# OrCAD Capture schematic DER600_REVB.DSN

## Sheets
1 PAGE1: size C; title: DER 802; rev: A
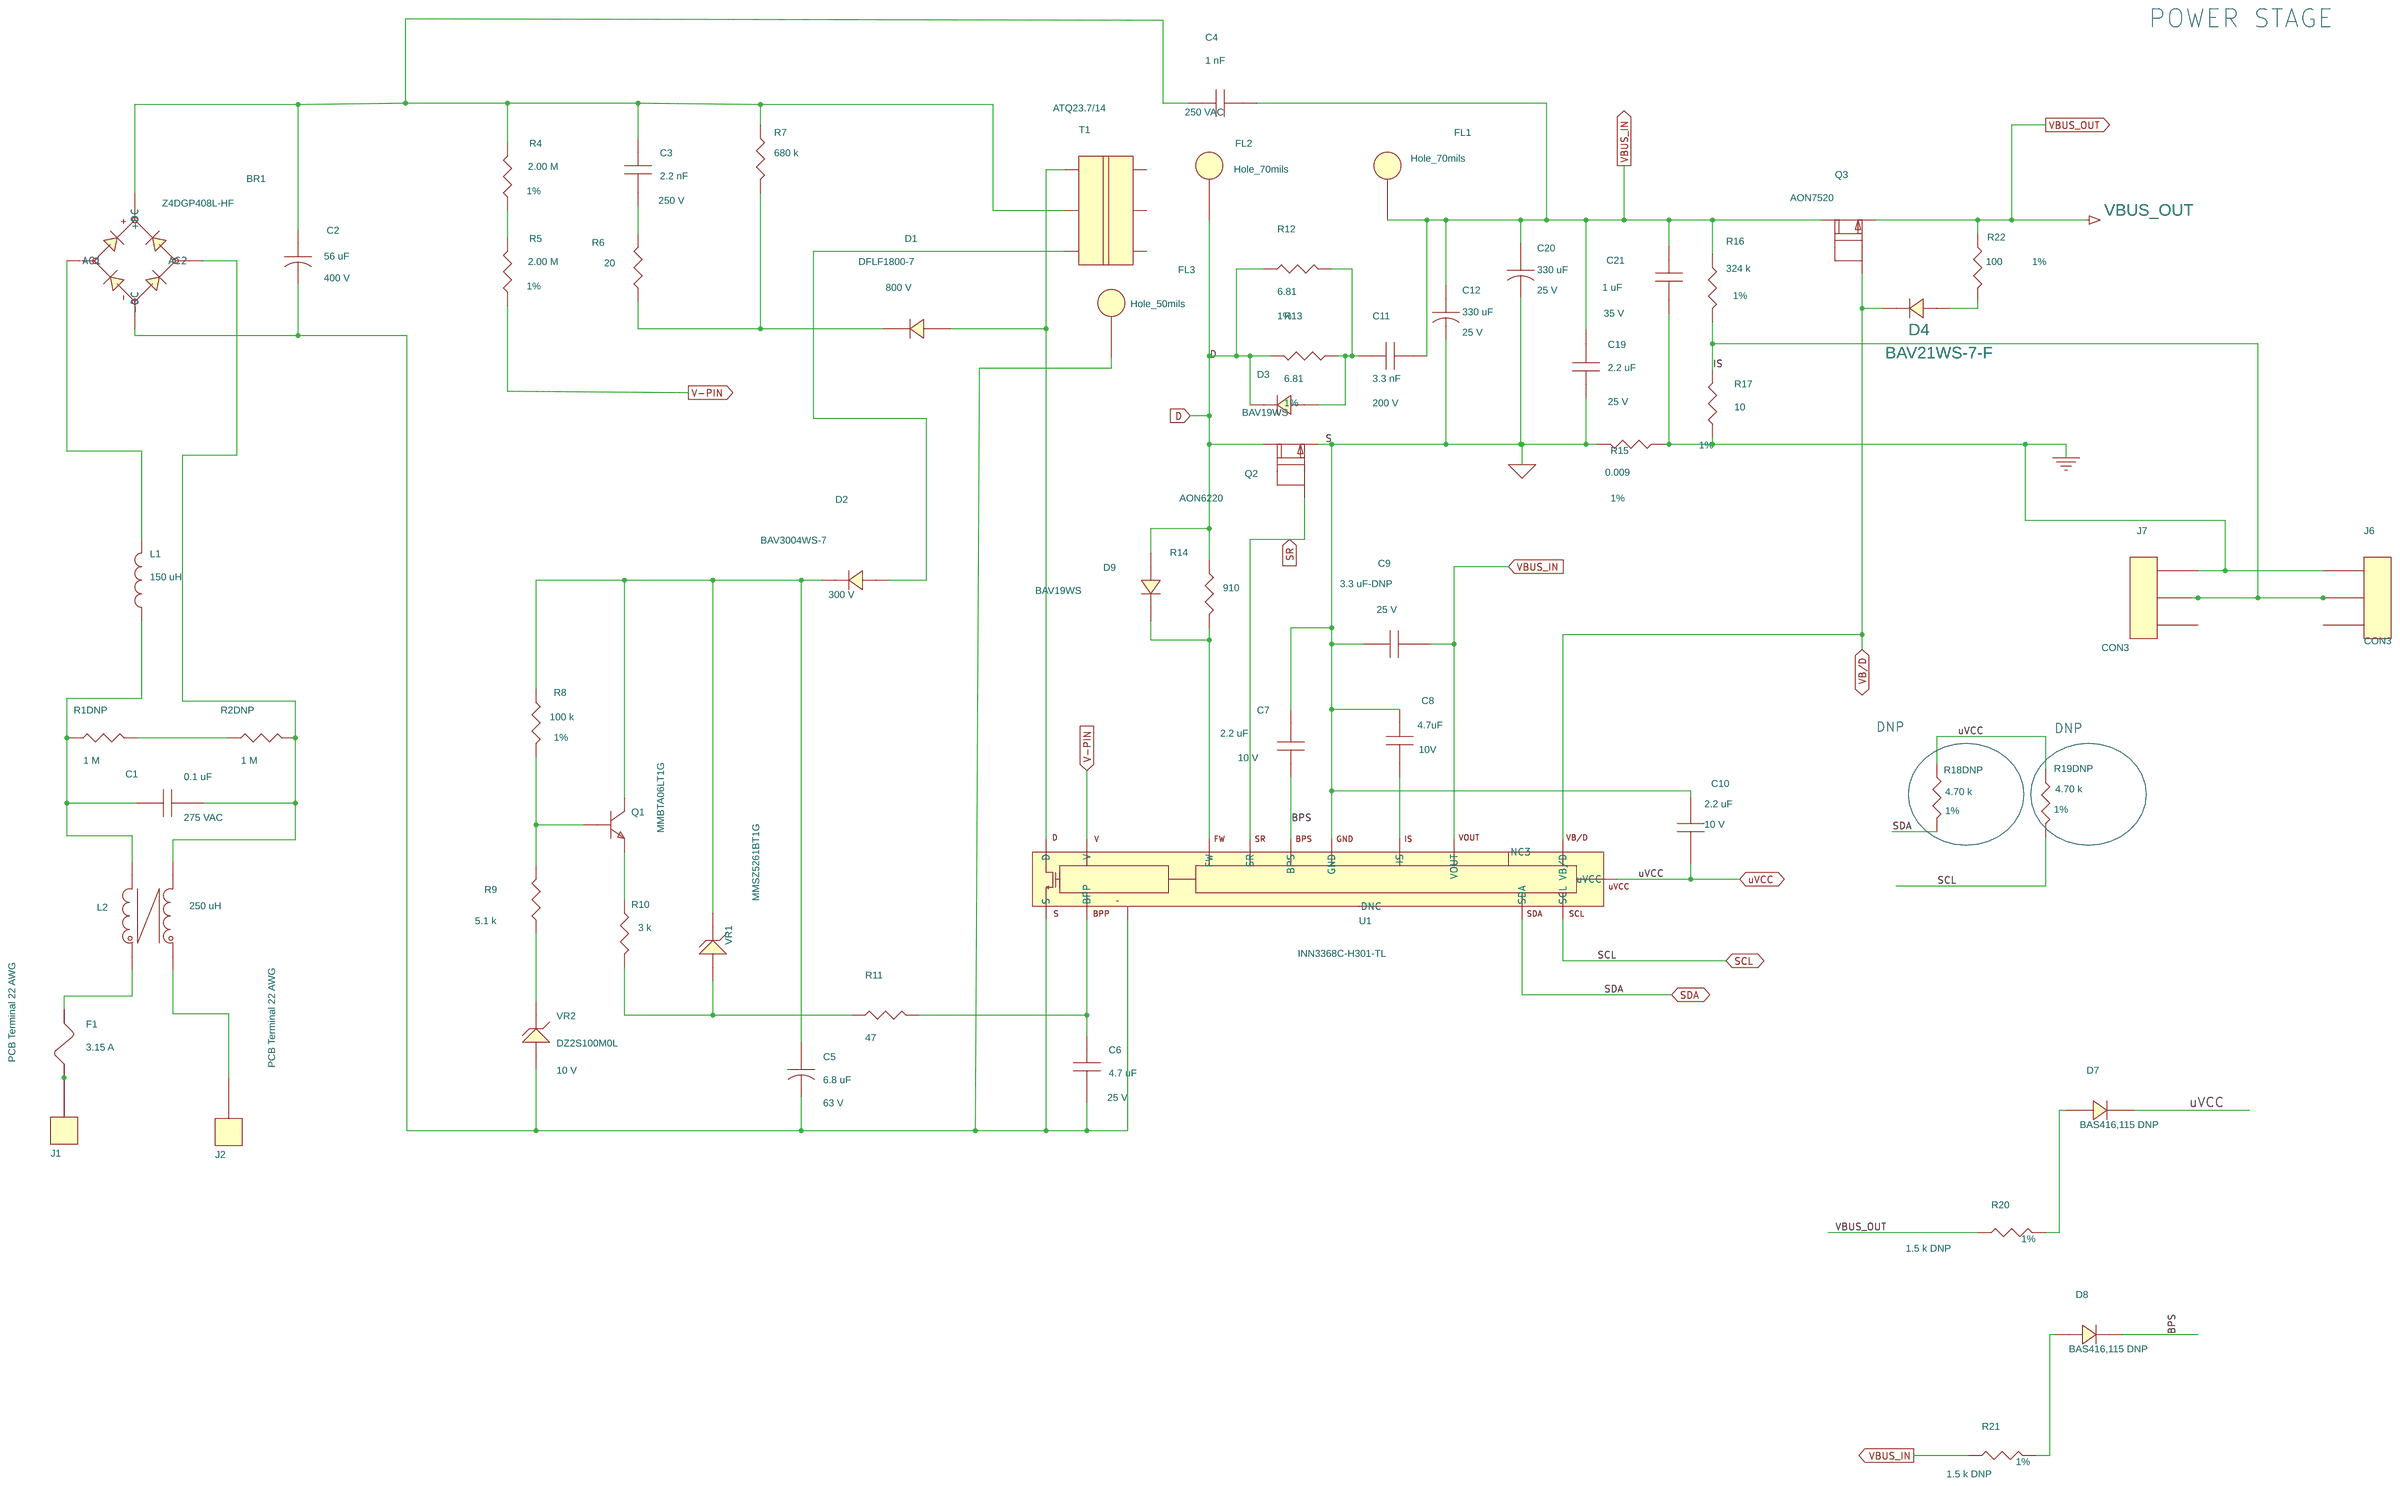
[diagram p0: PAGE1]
2 PAGE2: size Custom
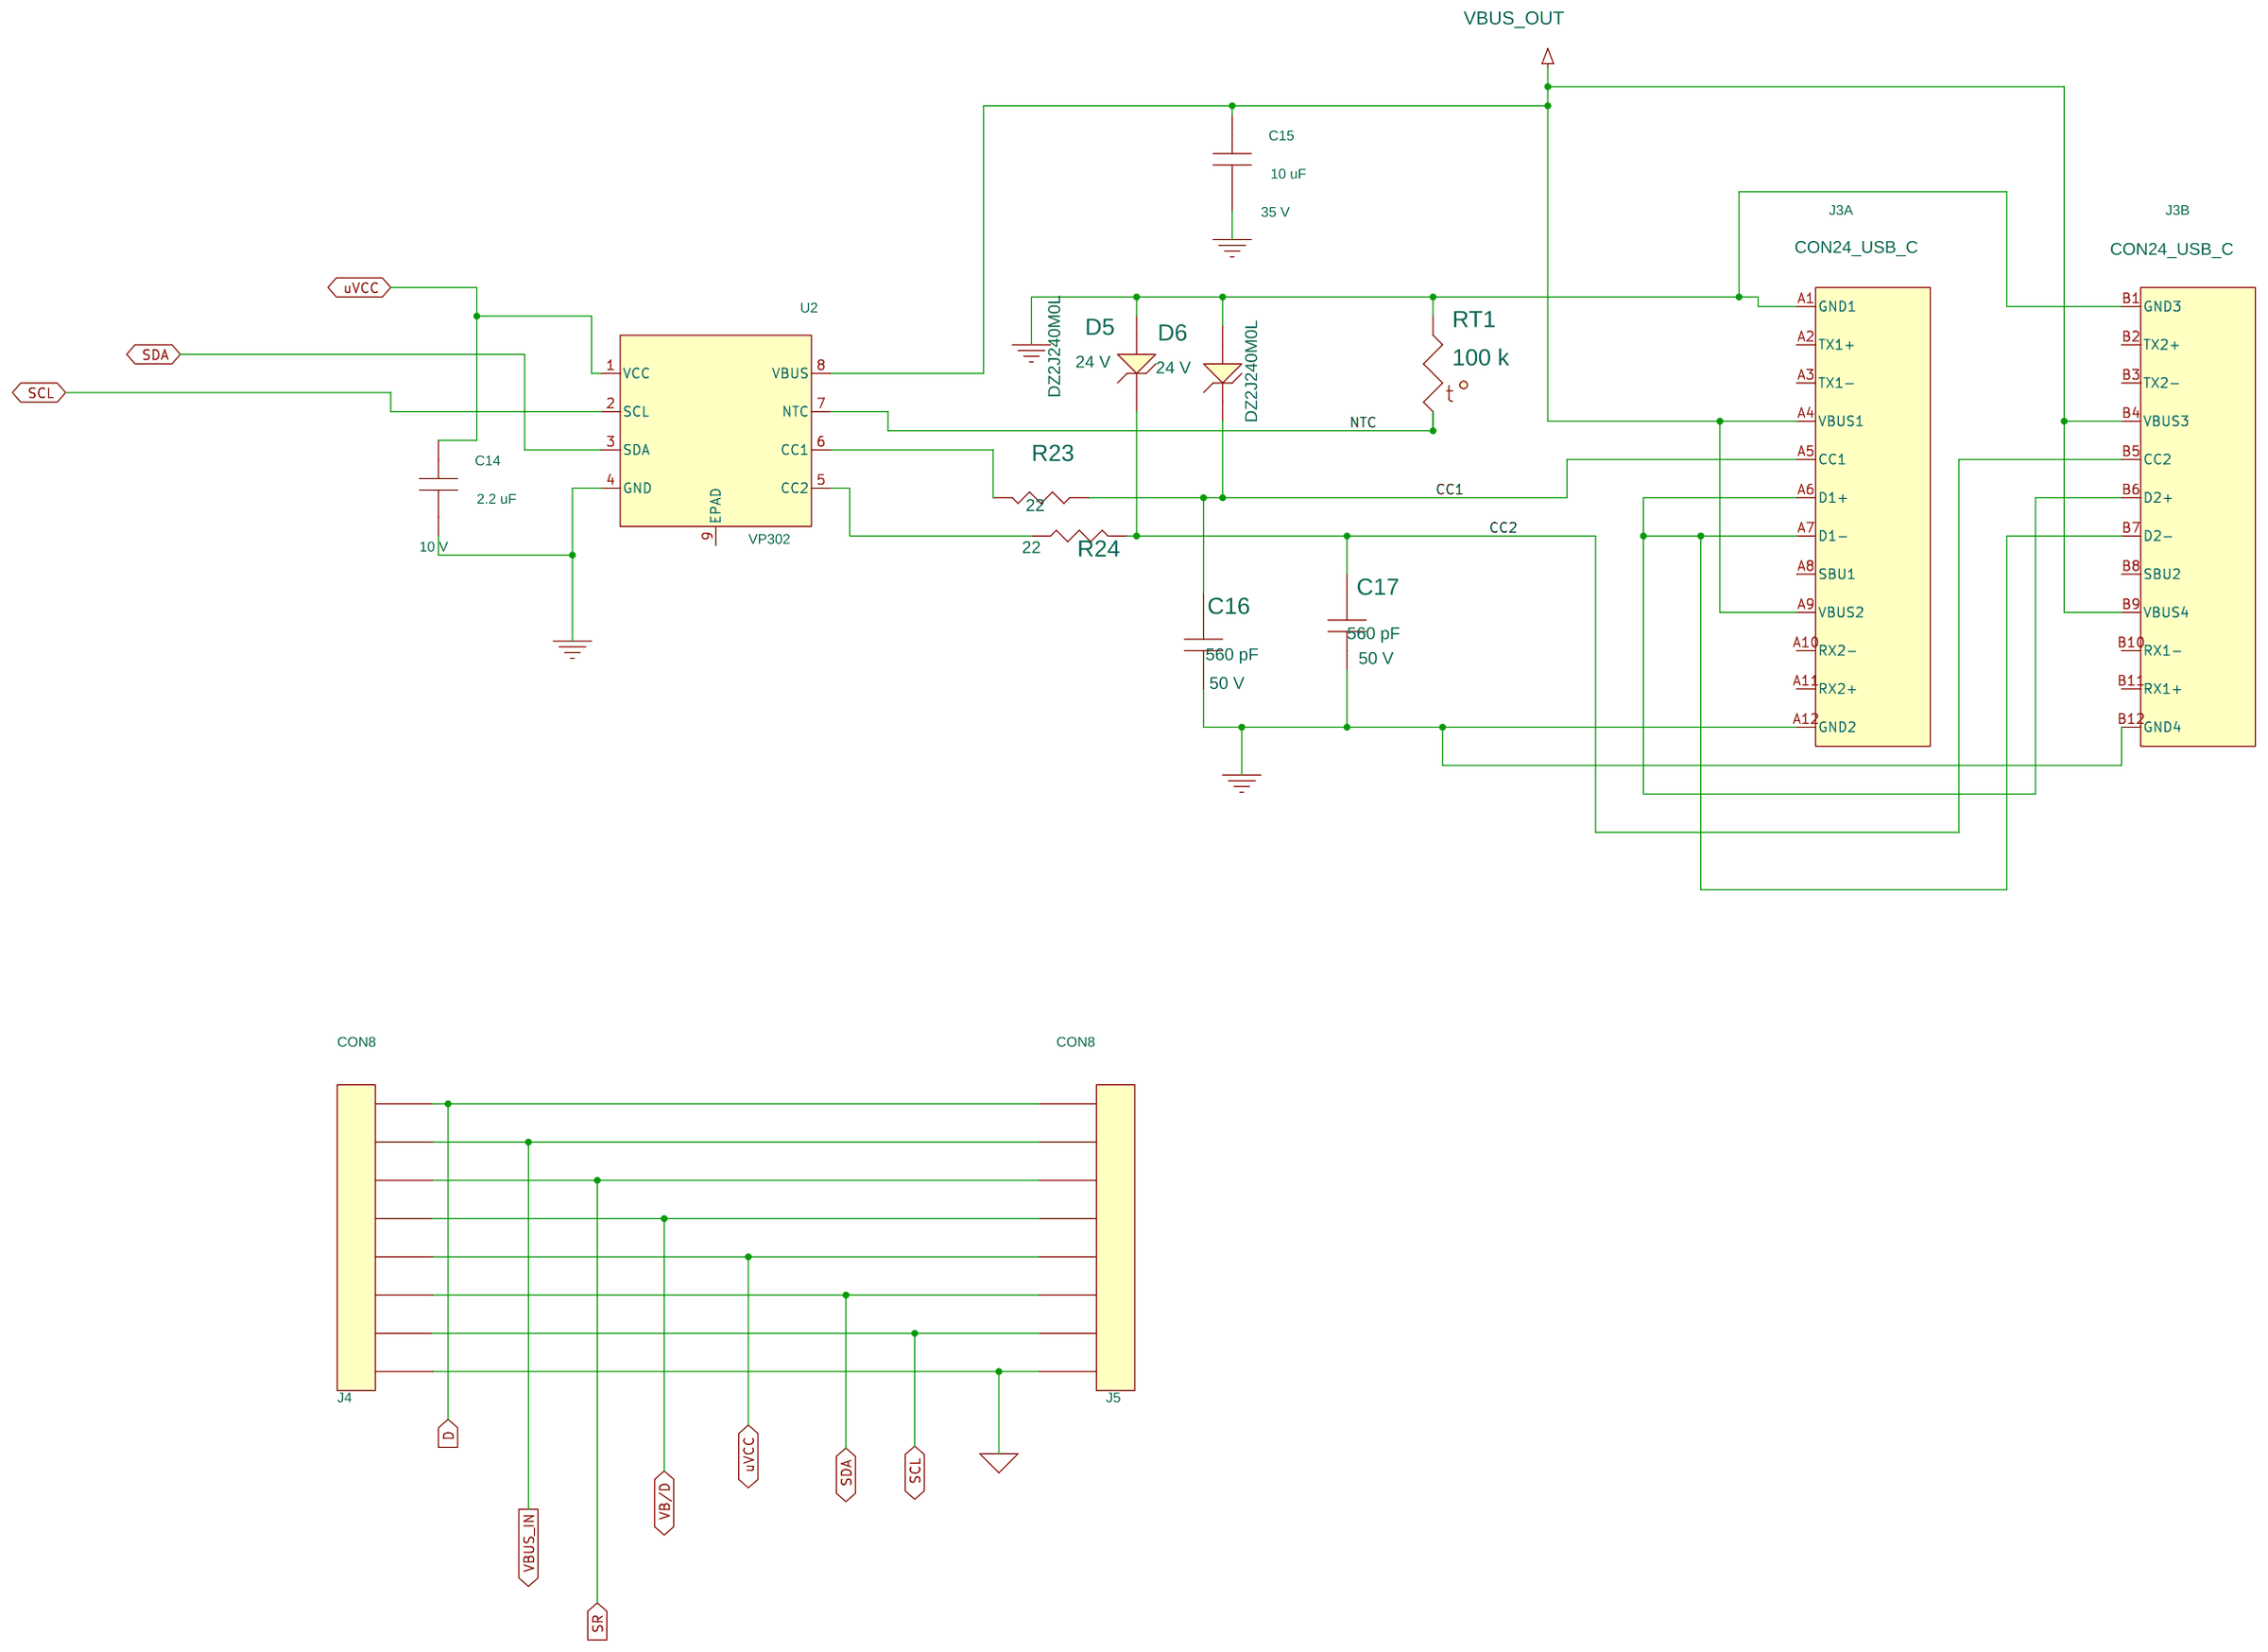
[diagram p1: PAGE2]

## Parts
sheet PAGE1
BR1  Z4DGP408L-HF  [pi_sm_d_z4d]
C1  0.1 uF  [pinpxcaprad5x13x11p1mm040]
C2  56 uF  [pipolcapclyd500ls200040]
C3  2.2 nF  [pismc0805]
C4  1 nF  [pinpycaprad540x290ls400040]
C5  6.8 uF  [pipolcap4p0x11p0xls1p5d030]
C6  4.7 uF  [pismc0805]
C7  2.2 uF  [pismc0603]
C8  4.7uF  [pismc0603]
C9  3.3 uF-DNP  [pismc0805]
C10  2.2 uF  [pismc0603]
C11  3.3 nF  [pismc0805]
C12  330 uF  [pipolcapcyld315ls138d030]
C19  2.2 uF  [pismc0805]
C20  330 uF  [pipolcapcyld315ls138d030]
C21  1 uF  [pismc0603]
D1  DFLF1800-7  [pismddflr120012]
D2  BAV3004WS-7  [pismsod323]
D3  BAV19WS  [pismsod323]
D4  BAV21WS-7-F  [pismsod323]
D7  BAS416,115 DNP  [pismdsod323]
D8  BAS416,115 DNP  [pismdsod323]
D9  BAV19WS  [pismsod323]
F1  3.15 A  [pi_rst_microfuse]
FL1  Hole_70mils  [pi_hole_70mil]
FL2  Hole_70mils  [pi_hole_70mil]
FL3  Hole_50mils  [pi_hole_50mil]
J1  PCB Terminal 22 AWG  [pi_hole_22awg]
J2  PCB Terminal 22 AWG  [pi_hole_22awg]
J6  CON3  [pi_hdr_1p27mm_3RA]
J7  CON3  [pi_hdr_1p27mm_3RA]
L1  150 uH  [pi2p16p5x8p5x8p5lsd60]
L2  250 uH  [pi_toroid_CMC4p_V_275uH]
Q1  MMBTA06LT1G  [pismsot23123_1]
Q2  AON6220  [pismpqfn5x6b]
Q3  AON7520  [pism8dfn_ep3p3x3p3a]
R1DNP  1 M  [pismr1206]
R2DNP  1 M  [pismr1206]
R4  2.00 M  [pismr1206]
R5  2.00 M  [pismr1206]
R6  20  [pismr1206]
R7  680 k  [pismr1206]
R8  100 k  [pismr0603]
R9  5.1 k  [pismr0805]
R10  3 k  [pismr0603]
R11  47  [pismr0603]
R12  6.81  [pismr1206]
R13  6.81  [pismr1206]
R14  910  [pismr0603]
R15  0.009  [pismr0805]
R16  324 k  [pismr0805]
R17  10  [pismr0603]
R18DNP  4.70 k  [pismr0402]
R19DNP  4.70 k  [pismr0402]
R20  1.5 k DNP  [pismr1206]
R21  1.5 k DNP  [pismr1206]
R22  100  [pismr0603]
T1  ATQ23.7/14  [pi_bobbin_ATQ23_7_H_6P]
U1  INN3368C-H301-TL  [pi_ic_insop_24d]
VR1  MMSZ5261BT1G  [pi_sm_sod-123_12]
VR2  DZ2S100M0L  [pi_sm_d_ssmini2p]
sheet PAGE2
C14  2.2 uF  [pismc0603]
C15  10 uF  [pismc0805]
C16  560 pF  [pismc0603]
C17  560 pF  [pismc0603]
D5  DZ2J240M0L  [pismsod323F]
D6  DZ2J240M0L  [pismsod323F]
J3  CON24_USB_C  [pi_conn_USBC_Wurth]  (sections A,B)
J4  CON8  [pi_hdr_1p27mm_8RA]
J5  CON8  [pi_hdr_1p27mm_8RA]
R23  22  [pismr0603]
R24  22  [pismr0603]
RT1  100 k  [pismr0603]
U2  VP302  [PI_SM_DFN-8]

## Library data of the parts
BR1 = DISCRETE_BRIDGE_+~~-: Part Number: 15-01113-00
C1 = CAP_NP: ALT_SYMBOLS: pinpxcaprad5x13x11p1mm040h; Disp_Voltage: 275 VAC; FPLIST: pinpxcaprad5x13x11p1mm040,pinpxcaprad5x13x11p1mm040h; Part Number: 20-09109-00; Voltage: 275 VAC
C2 = CAP_POL: ALT_SYMBOLS: pipolcapclyd500ls2000401000lh; Disp_Voltage: 400 V; FPLIST: pipolcapclyd500ls200040,pipolcapclyd500ls2000401000lh; Part Number: 20-01387-00; Voltage: 400 V
C3 = CAP_NP: Disp_Voltage: 250 V; Part Number: 20-08766-00; Voltage: 250 V
C4 = CAP_NP: ALT_SYMBOLS: pinpycaprad540x290ls400040h,pinpycaprad500x220ls400040; Disp_Voltage: 250 VAC; FPLIST: pinpycaprad540x290ls400040,pinpycaprad540x290ls400040h,pinpycaprad500x220ls400040; Part Number: 20-00375-00; Voltage: 250 VAC
C5 = CAP_POL: ALT_SYMBOLS: pipolcap4p0x11p0xls1p5d030h; Disp_Voltage: 63 V; FPLIST: pipolcap4p0x11p0xls1p5d030,pipolcap4p0x11p0xls1p5d030h; Part Number: 20-09108-00; Voltage: 63 V
C6 = CAP_NP: Disp_Voltage: 25 V; Part Number: 20-09137-00; Voltage: 16 V
C7 C10 C14 = CAP_NP: ALT_SYMBOLS: pismc0603_1; Disp_Voltage: 10 V; FPLIST: pismc0603,pismc0603_1; Part Number: 20-08740-00; Voltage: 10V
C8 = CAP_NP: Disp_Voltage: 10V; Part Number: 20-08591-00; Voltage: 10 V
C9 = CAP_NP: Disp_Voltage: 25 V; Part Number: 20-01041-00; Voltage: 25 V
C11 = CAP_NP: Disp_Voltage: 200 V; Part Number: 20-00956-00; Voltage: 200 V
C12 C20 = CAP_POL: ALT_SYMBOLS: pipolcapcyld315ls138d030h; Disp_Voltage: 25 V; FPLIST: pipolcapcyld315ls138d030,pipolcapcyld315ls138d030h; Part Number: 20-09107-00; Voltage: 25 V
C19 = CAP_NP: Disp_Voltage: 25 V; Part Number: 20-08603-00; Voltage: 25 V
C21 = CAP_NP: ALT_SYMBOLS: pismc0603_1; Disp_Voltage: 35 V; FPLIST: pismc0603,pismc0603_1; Part Number: 20-09172-00; Voltage: 35 V
D1 = DIODE: ALT_SYMBOLS: pismddflr120012_1; COMPGROUP: 2; Disp_Voltage: 800 V; FPLIST: pismddflr120012,pismddflr120012_1; Part Number: 15-01244-00
D2 = DIODE: COMPGROUP: 1; Disp_Voltage: 300 V; Part Number: 15-01138-00
D3 D9 = DIODE: Part Number: 15-00658-00
D4 = DIODE: COMPGROUP: 1; Part Number: 15-00385-00
D7 D8 = DIODE: Part Number: 15-01164-00
F1 = FUSE: ALT_SYMBOLS: pirstmicrofusehoz; FPLIST: pi_rst_microfuse,pirstmicrofusehoz; Part Number: 40-00020-00
FL1 FL2 = FlyingLead: Part Number: 35-00282-00
FL3 = FlyingLead: Part Number: 35-00283-00
J1 J2 = TERM_1Pin: Part Number: 35-00008-00
J6 J7 = CON3: ALT_SYMBOLS: pi_hdr_1p27mm_3RA_MB,pi_hdr_1p27mm_3RA_DNL; Part Number: 35-00481-00
L1 = INDUCTOR: Part Number: 32-00371-00
L2 = TORRID_4P_12_34: ALT_SYMBOLS: pi_toroid_CMC4p_V,pi_toroid_CMC4p_V_275uH; FPLIST: pi_toroid_CMC4p_H,pi_toroid_CMC4p_V,pi_toroid_CMC4p_V_275uH; Part Number: 32-00347-00
Q1 = NPN_BEC: Part Number: 55-00072-00
Q2 = FET_N_SGD_123_4_5678: Part Number: 50-00276-00
Q3 = FET_N_SGD_123_4_5678: Part Number: 50-00281-00
R1DNP R2DNP = R: Part Number: 05-01424-00
R4 R5 = R: Disp_Tol: 1%; Part Number: 05-03156-00
R6 = R: Part Number: 05-01311-00
R7 = R: Part Number: 05-01420-00
R8 = R: Disp_Tol: 1%; Part Number: 05-01174-00
R9 = R: Part Number: 05-01536-00
R10 = R: Part Number: 05-01699-00
R11 = R: ALT_SYMBOLS: pismr0603_1; Part Number: 05-01656-00
R12 R13 = R: Disp_Tol: 1%; Part Number: 05-06303-00
R14 = R: Part Number: 05-01687-00
R15 = R: Disp_Tol: 1%; Part Number: 05-06508-00
R16 = R: Disp_Tol: 1%; Part Number: 05-00829-00
R17 = R: Disp_Tol: 1%; Part Number: 05-00886-00
R18DNP R19DNP = R: Disp_Tol: 1%; Part Number: 05-05899-00
R20 R21 = R: Disp_Tol: 1%; Part Number: 05-00210-00
R22 = R: Disp_Tol: 1%; Part Number: 05-00982-00
T1 = BATQ23_7_6P_GENERIC: FPLIST: pi_bobbin_ATQ23_7_H_4P,pi_bobbin_ATQ23_7_H_6P; Part Number: 25-01171-00
U1 = InnoPro_p15: Part Number: 10-01054-00
VR1 = DIODE_ZENER: Part Number: 15-01102-00
VR2 = DIODE_ZENER: Disp_Voltage: 10 V; Part Number: 15-00926-00
C15 = CAP_NP: ALT_SYMBOLS: pismc0805_1; Disp_Voltage: 35 V; FPLIST: pismc0805,pismc0805_1; Part Number: 20-08720-00; ROOM: 3; Voltage: 35 V
C16 C17 = CAP_NP: Disp_Voltage: 50 V; Part Number: 20-08982-00; ROOM: 3; Voltage: 50 V
D5 D6 = DIODE_ZENER: Disp_Voltage: 24 V; Part Number: 15-01042-00; ROOM: 3
J3 = CON24_USB: Part Number: 35-00414-00; ROOM: 3
J4 J5 = CON8: Part Number: 35-00433-00
R23 R24 = R: COMPGROUP: 1; Part Number: 05-01648-00; ROOM: 3
RT1 = THERMISTOR: Part Number: 90-00063-00; ROOM: 3
U2 = VP302: Part Number: 45-00495-00; ROOM: 3

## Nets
GND: C14.2 C15.2 C16.1 C17.1 C21.2 D5.2 D6.2 J3.A1(GND1) J3.A12(GND2) J3.B1(GND3) J3.B12(GND4) J6.1 J7.1 R15.1 R17.1 RT1.1 U2.4(GND)
GND_SIGNAL: C7.2 C8.1 C9.1 C10.1 C12.2 C19.1 C20.2 J4.8 J5.8 Q2.1(S) R15.2 U1.2(GND)
VBUS_IN: C4.2 C9.2 C11.2 C12.1 C19.2 C20.1 C21.1 FL1.1 J4.2 J5.2 Q3.5(D) R16.1 R21.1 U1.10(VOUT)
VBUS_OUT: C15.1 J3.A4(VBUS1) J3.A9(VBUS2) J3.B4(VBUS3) J3.B9(VBUS4) Q3.1(S) R20.1 R22.1 U2.8(VBUS)
BPS: C7.1 D8.1 U1.4(BPS)
CC1: C16.2 D6.1 J3.A5(CC1) R23.2
CC2: C17.2 D5.1 J3.B5(CC2) R24.1
D: D3.1 D9.2 FL2.1 J4.1 J5.1 Q2.5(D) R12.1 R13.2 R14.1
IS: J6.2 J7.2 R16.2 R17.2
NC3: U1.3(NC3)
NTC: RT1.2 U2.7(NTC)
SCL: J4.7 J5.7 R19DNP.2 U1.5(SCL) U2.2(SCL)
SDA: J4.6 J5.6 R18DNP.2 U1.6(SDA) U2.3(SDA)
SR: J4.3 J5.3 Q2.4(G) U1.9(SR)
uVCC: C10.2 C14.1 D7.1 J4.5 J5.5 R18DNP.1 R19DNP.1 U1.7(uVCC) U2.1(VCC)
V-PIN: R5.1 U1.13(V)
VB/D: D4.1 J4.4 J5.4 Q3.4(G) U1.8(VB/D)
N10479111: F1.1 J1.1
N10805923: BR1.4(-DC) C2.2 C5.2 C6.2 FL3.1 U1.15 U1.16(S) VR2.2
N10806149: C6.1 R11.2 U1.14(BPP)
N10813018: R4.1 R5.2
N10873526: D9.1 R14.2 U1.11(FW)
N10950085: R10.2 R11.1 VR1.2
N10950141: Q1.2(EMITTER) R10.1
N10950189: Q1.1(BASE) R8.2 R9.1
N10961861: BR1.1(+DC) C2.1 C3.1 C4.1 R4.2 R7.1 T1.2
N10966650: D1.2 T1.1 U1.24(D)
N11036082: D1.1 R6.1 R7.2
N11077448: C5.1 D2.1 Q1.3(COLLECTOR) R8.1 VR1.1
N11099981: BR1.2(AC1) L1.2
N11100009: C1.1 L1.1 L2.4 R1DNP.1
N11100013: BR1.3(AC2) C1.2 L2.2 R2DNP.2
N11100133: J2.1 L2.1
N11120095: D2.2 T1.3
N11139619: C3.2 R6.2
N11156493: C11.1 D3.2 R12.2 R13.1
N11381159: R1DNP.2 R2DNP.1
N12152275: D4.2 R22.2
N12155633: C8.2 U1.1(IS)
N12168266: R9.2 VR2.1
N12183858: R23.1 U2.6(CC1)
N12183920: R24.2 U2.5(CC2)
N12183972: J3.A6(D1+) J3.A7(D1-) J3.B6(D2+) J3.B7(D2-)
N12291187: D7.2 R20.2
N12330267: F1.2 L2.3
N12333123: D8.2 R21.2

Not connected (* = marked no-connect by the designer): J3 A2(TX1+) A3(TX1-) A8(SBU1) A10(RX2-) A11(RX2+) B2(TX2+) B3(TX2-) B8(SBU2) B10(RX1-) B11(RX1+); J6 3; J7 3; Q2 2(S2) 3(S3) 6(D6) 7(D7) 8(D8); Q3 2(S2) 3(S3) 6(D6) 7(D7) 8(D8); T1 4 5 6; U1 12(DNC); U2 9(EPAD)

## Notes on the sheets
sheet 1
- POWER STAGE
- DNP
- DNP
